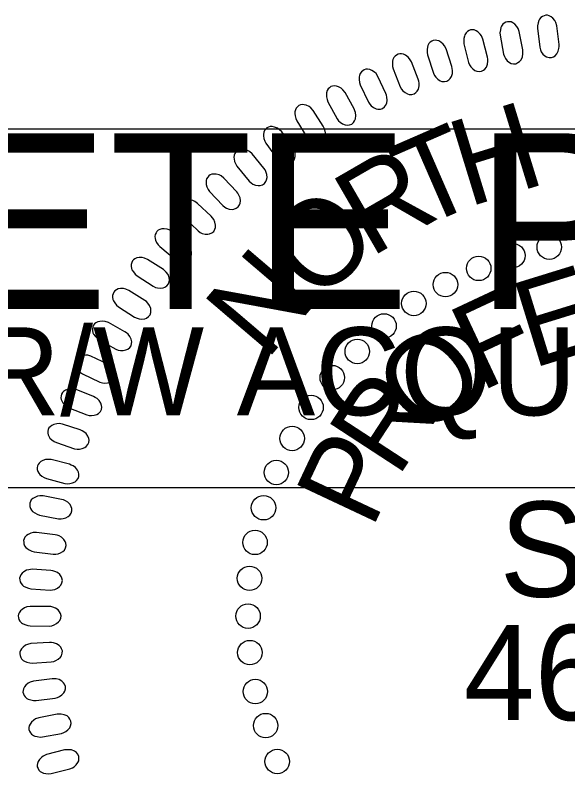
# Model space of a CAD drawing. Extents: x 502400 to 509344, y 448070 to 484209.
# Drawn here: x 507178.88 to 507215.05, y 484083.77 to 484133.46 of the extents above; entities that cross this region are included whole.
import ezdxf

# ---------------------------------------------------------------- set-up
doc = ezdxf.new("R2010")
doc.units = 0
doc.layers.add('Sheet PE Seal Cell', color=7, linetype='Continuous')
doc.layers.add('Sheet Sticker Incomplete CELL', color=7, linetype='Continuous')

msp = doc.modelspace()

# ---------------------------------------------------------------- linework, layer by layer
at = {"layer": 'Sheet PE Seal Cell'}
for points in [[(507212.1, 484131.181), (507211.871, 484132.386), (507211.793, 484132.594), (507211.716, 484132.722), (507211.574, 484132.868), (507211.458, 484132.957), (507211.333, 484133.015), (507211.223, 484133.034), (507211.109, 484133.033), (507211.002, 484132.992), (507210.891, 484132.94), (507210.799, 484132.862), (507210.714, 484132.744), (507210.671, 484132.655), (507210.633, 484132.495), (507210.608, 484132.308), (507210.615, 484132.147), (507210.843, 484130.911), (507210.897, 484130.749), (507210.967, 484130.62), (507211.085, 484130.48), (507211.221, 484130.364), (507211.332, 484130.304), (507211.497, 484130.274), (507211.647, 484130.283), (507211.787, 484130.35), (507211.881, 484130.419), (507211.987, 484130.54), (507212.073, 484130.729), (507212.105, 484130.918), (507212.11, 484131.051)], [(507214.482, 484131.549), (507214.328, 484132.766), (507214.264, 484132.98), (507214.194, 484133.111), (507214.062, 484133.266), (507213.952, 484133.362), (507213.831, 484133.427), (507213.722, 484133.454), (507213.608, 484133.46), (507213.499, 484133.426), (507213.384, 484133.381), (507213.288, 484133.309), (507213.196, 484133.197), (507213.147, 484133.11), (507213.099, 484132.953), (507213.062, 484132.768), (507213.06, 484132.607), (507213.21, 484131.359), (507213.253, 484131.194), (507213.315, 484131.06), (507213.424, 484130.913), (507213.553, 484130.789), (507213.659, 484130.722), (507213.822, 484130.682), (507213.973, 484130.681), (507214.116, 484130.739), (507214.214, 484130.802), (507214.328, 484130.917), (507214.425, 484131.1), (507214.469, 484131.286), (507214.483, 484131.419)], [(507209.795, 484130.709), (507209.491, 484131.897), (507209.4, 484132.1), (507209.314, 484132.223), (507209.164, 484132.359), (507209.042, 484132.441), (507208.914, 484132.491), (507208.802, 484132.504), (507208.689, 484132.495), (507208.585, 484132.448), (507208.477, 484132.389), (507208.39, 484132.305), (507208.314, 484132.182), (507208.276, 484132.091), (507208.247, 484131.929), (507208.234, 484131.74), (507208.252, 484131.58), (507208.557, 484130.361), (507208.621, 484130.202), (507208.699, 484130.078), (507208.826, 484129.946), (507208.969, 484129.838), (507209.083, 484129.786), (507209.25, 484129.766), (507209.4, 484129.784), (507209.535, 484129.86), (507209.624, 484129.934), (507209.722, 484130.062), (507209.795, 484130.256), (507209.816, 484130.447), (507209.813, 484130.579)], [(507207.461, 484130.088), (507207.083, 484131.255), (507206.98, 484131.452), (507206.887, 484131.569), (507206.728, 484131.696), (507206.602, 484131.77), (507206.47, 484131.811), (507206.358, 484131.817), (507206.246, 484131.801), (507206.145, 484131.748), (507206.041, 484131.682), (507205.96, 484131.594), (507205.891, 484131.466), (507205.859, 484131.372), (507205.84, 484131.208), (507205.839, 484131.019), (507205.867, 484130.86), (507206.248, 484129.663), (507206.322, 484129.509), (507206.407, 484129.39), (507206.542, 484129.266), (507206.692, 484129.168), (507206.809, 484129.122), (507206.977, 484129.113), (507207.125, 484129.14), (507207.255, 484129.224), (507207.339, 484129.304), (507207.429, 484129.438), (507207.49, 484129.637), (507207.499, 484129.828), (507207.487, 484129.961)], [(507205.261, 484129.272), (507204.809, 484130.413), (507204.694, 484130.603), (507204.594, 484130.714), (507204.427, 484130.83), (507204.297, 484130.897), (507204.163, 484130.929), (507204.051, 484130.928), (507203.94, 484130.905), (507203.843, 484130.845), (507203.742, 484130.773), (507203.667, 484130.679), (507203.606, 484130.548), (507203.58, 484130.452), (507203.572, 484130.288), (507203.583, 484130.099), (507203.621, 484129.943), (507204.076, 484128.771), (507204.159, 484128.622), (507204.253, 484128.509), (507204.395, 484128.393), (507204.55, 484128.305), (507204.67, 484128.266), (507204.838, 484128.268), (507204.984, 484128.305), (507205.108, 484128.397), (507205.187, 484128.482), (507205.269, 484128.621), (507205.318, 484128.823), (507205.314, 484129.015), (507205.295, 484129.146)], [(507203.143, 484128.339), (507202.621, 484129.449), (507202.494, 484129.631), (507202.387, 484129.736), (507202.214, 484129.842), (507202.079, 484129.9), (507201.944, 484129.924), (507201.832, 484129.916), (507201.722, 484129.886), (507201.629, 484129.82), (507201.534, 484129.743), (507201.464, 484129.644), (507201.412, 484129.509), (507201.392, 484129.411), (507201.395, 484129.247), (507201.417, 484129.059), (507201.464, 484128.905), (507201.993, 484127.766), (507202.085, 484127.621), (507202.185, 484127.514), (507202.334, 484127.408), (507202.495, 484127.329), (507202.617, 484127.298), (507202.784, 484127.311), (507202.928, 484127.356), (507203.046, 484127.456), (507203.12, 484127.546), (507203.192, 484127.69), (507203.229, 484127.894), (507203.213, 484128.085), (507203.185, 484128.216)], [(507201.06, 484127.325), (507200.469, 484128.401), (507200.331, 484128.575), (507200.218, 484128.672), (507200.038, 484128.767), (507199.9, 484128.816), (507199.764, 484128.832), (507199.653, 484128.816), (507199.545, 484128.78), (507199.456, 484128.709), (507199.366, 484128.625), (507199.303, 484128.522), (507199.259, 484128.384), (507199.245, 484128.285), (507199.258, 484128.122), (507199.292, 484127.935), (507199.349, 484127.785), (507199.948, 484126.68), (507200.049, 484126.542), (507200.156, 484126.442), (507200.311, 484126.345), (507200.477, 484126.276), (507200.6, 484126.253), (507200.767, 484126.276), (507200.907, 484126.331), (507201.019, 484126.438), (507201.087, 484126.532), (507201.15, 484126.681), (507201.173, 484126.887), (507201.146, 484127.077), (507201.109, 484127.204)], [(507199.043, 484126.183), (507198.386, 484127.219), (507198.237, 484127.385), (507198.118, 484127.474), (507197.933, 484127.558), (507197.792, 484127.598), (507197.655, 484127.606), (507197.544, 484127.583), (507197.439, 484127.54), (507197.355, 484127.463), (507197.27, 484127.374), (507197.214, 484127.267), (507197.179, 484127.127), (507197.171, 484127.028), (507197.194, 484126.865), (507197.24, 484126.682), (507197.306, 484126.534), (507197.973, 484125.469), (507198.083, 484125.338), (507198.196, 484125.244), (507198.357, 484125.158), (507198.526, 484125.1), (507198.651, 484125.084), (507198.816, 484125.118), (507198.952, 484125.181), (507199.058, 484125.295), (507199.119, 484125.393), (507199.173, 484125.545), (507199.183, 484125.753), (507199.144, 484125.941), (507199.1, 484126.065)], [(507197.042, 484124.829), (507196.321, 484125.821), (507196.162, 484125.977), (507196.038, 484126.059), (507195.847, 484126.131), (507195.704, 484126.162), (507195.567, 484126.161), (507195.458, 484126.132), (507195.356, 484126.082), (507195.277, 484126), (507195.198, 484125.906), (507195.149, 484125.796), (507195.122, 484125.653), (507195.121, 484125.554), (507195.155, 484125.393), (507195.211, 484125.213), (507195.287, 484125.07), (507196.019, 484124.049), (507196.137, 484123.925), (507196.255, 484123.838), (507196.421, 484123.762), (507196.594, 484123.715), (507196.72, 484123.707), (507196.882, 484123.751), (507197.015, 484123.823), (507197.112, 484123.943), (507197.167, 484124.045), (507197.212, 484124.2), (507197.209, 484124.408), (507197.158, 484124.593), (507197.106, 484124.715)], [(507195.162, 484123.44), (507194.38, 484124.385), (507194.212, 484124.53), (507194.082, 484124.605), (507193.888, 484124.664), (507193.743, 484124.687), (507193.606, 484124.677), (507193.5, 484124.64), (507193.401, 484124.584), (507193.327, 484124.497), (507193.254, 484124.398), (507193.211, 484124.286), (507193.194, 484124.142), (507193.199, 484124.042), (507193.242, 484123.884), (507193.31, 484123.708), (507193.395, 484123.57), (507194.189, 484122.597), (507194.315, 484122.481), (507194.439, 484122.402), (507194.609, 484122.336), (507194.785, 484122.3), (507194.911, 484122.3), (507195.07, 484122.354), (507195.198, 484122.434), (507195.287, 484122.56), (507195.336, 484122.665), (507195.371, 484122.823), (507195.354, 484123.03), (507195.292, 484123.211), (507195.232, 484123.33)], [(507193.374, 484121.9), (507192.535, 484122.795), (507192.357, 484122.93), (507192.223, 484122.996), (507192.025, 484123.043), (507191.88, 484123.056), (507191.744, 484123.038), (507191.64, 484122.995), (507191.544, 484122.933), (507191.476, 484122.842), (507191.409, 484122.738), (507191.374, 484122.623), (507191.366, 484122.478), (507191.377, 484122.379), (507191.43, 484122.224), (507191.51, 484122.052), (507191.602, 484121.921), (507192.457, 484120.999), (507192.589, 484120.891), (507192.717, 484120.82), (507192.892, 484120.765), (507193.07, 484120.739), (507193.195, 484120.747), (507193.35, 484120.812), (507193.473, 484120.9), (507193.554, 484121.031), (507193.597, 484121.139), (507193.622, 484121.299), (507193.593, 484121.504), (507193.518, 484121.681), (507193.452, 484121.796)], [(507191.712, 484120.291), (507190.818, 484121.131), (507190.632, 484121.254), (507190.495, 484121.312), (507190.294, 484121.346), (507190.148, 484121.351), (507190.013, 484121.323), (507189.912, 484121.274), (507189.821, 484121.206), (507189.759, 484121.111), (507189.699, 484121.003), (507189.67, 484120.887), (507189.671, 484120.742), (507189.689, 484120.643), (507189.751, 484120.492), (507189.841, 484120.326), (507189.942, 484120.199), (507190.853, 484119.334), (507190.992, 484119.234), (507191.124, 484119.171), (507191.302, 484119.127), (507191.48, 484119.114), (507191.605, 484119.129), (507191.757, 484119.203), (507191.873, 484119.298), (507191.946, 484119.435), (507191.982, 484119.545), (507191.996, 484119.706), (507191.955, 484119.909), (507191.87, 484120.081), (507191.796, 484120.191)], [(507190.098, 484118.504), (507189.154, 484119.287), (507188.96, 484119.398), (507188.82, 484119.447), (507188.617, 484119.468), (507188.471, 484119.464), (507188.339, 484119.428), (507188.241, 484119.373), (507188.154, 484119.299), (507188.098, 484119.2), (507188.045, 484119.088), (507188.024, 484118.97), (507188.034, 484118.826), (507188.057, 484118.729), (507188.13, 484118.582), (507188.23, 484118.421), (507188.338, 484118.302), (507189.301, 484117.495), (507189.446, 484117.404), (507189.583, 484117.35), (507189.763, 484117.317), (507189.941, 484117.314), (507190.065, 484117.339), (507190.211, 484117.421), (507190.322, 484117.523), (507190.387, 484117.664), (507190.415, 484117.777), (507190.419, 484117.938), (507190.365, 484118.138), (507190.27, 484118.305), (507190.188, 484118.41)], [(507188.574, 484116.802), (507187.544, 484117.468), (507187.339, 484117.555), (507187.193, 484117.588), (507186.99, 484117.586), (507186.845, 484117.563), (507186.718, 484117.512), (507186.628, 484117.446), (507186.55, 484117.363), (507186.505, 484117.258), (507186.466, 484117.141), (507186.459, 484117.021), (507186.486, 484116.879), (507186.52, 484116.785), (507186.61, 484116.648), (507186.728, 484116.499), (507186.85, 484116.394), (507187.901, 484115.706), (507188.056, 484115.633), (507188.197, 484115.595), (507188.38, 484115.584), (507188.558, 484115.602), (507188.678, 484115.641), (507188.813, 484115.74), (507188.911, 484115.854), (507188.959, 484116.002), (507188.974, 484116.117), (507188.959, 484116.278), (507188.882, 484116.47), (507188.767, 484116.624), (507188.674, 484116.719)], [(507187.359, 484114.779), (507186.324, 484115.437), (507186.119, 484115.523), (507185.973, 484115.554), (507185.769, 484115.551), (507185.625, 484115.527), (507185.497, 484115.475), (507185.408, 484115.408), (507185.33, 484115.324), (507185.287, 484115.218), (507185.249, 484115.102), (507185.243, 484114.981), (507185.271, 484114.84), (507185.306, 484114.746), (507185.397, 484114.609), (507185.516, 484114.462), (507185.639, 484114.358), (507186.696, 484113.678), (507186.851, 484113.606), (507186.993, 484113.569), (507187.175, 484113.559), (507187.353, 484113.579), (507187.473, 484113.618), (507187.607, 484113.719), (507187.704, 484113.835), (507187.751, 484113.982), (507187.765, 484114.097), (507187.749, 484114.258), (507187.67, 484114.449), (507187.554, 484114.603), (507187.461, 484114.698)], [(507186.056, 484112.73), (507184.981, 484113.322), (507184.771, 484113.395), (507184.623, 484113.416), (507184.421, 484113.4), (507184.277, 484113.367), (507184.154, 484113.308), (507184.069, 484113.235), (507183.997, 484113.147), (507183.961, 484113.039), (507183.929, 484112.92), (507183.931, 484112.799), (507183.968, 484112.659), (507184.009, 484112.569), (507184.107, 484112.437), (507184.236, 484112.298), (507184.365, 484112.202), (507185.462, 484111.59), (507185.621, 484111.527), (507185.765, 484111.5), (507185.949, 484111.501), (507186.125, 484111.532), (507186.242, 484111.579), (507186.37, 484111.687), (507186.459, 484111.809), (507186.496, 484111.959), (507186.503, 484112.074), (507186.477, 484112.234), (507186.386, 484112.42), (507186.262, 484112.566), (507186.162, 484112.655)], [(507184.947, 484110.606), (507183.837, 484111.129), (507183.623, 484111.189), (507183.474, 484111.201), (507183.273, 484111.172), (507183.132, 484111.131), (507183.013, 484111.063), (507182.932, 484110.985), (507182.866, 484110.892), (507182.836, 484110.783), (507182.813, 484110.661), (507182.822, 484110.542), (507182.868, 484110.405), (507182.914, 484110.317), (507183.021, 484110.192), (507183.158, 484110.061), (507183.292, 484109.972), (507184.427, 484109.43), (507184.589, 484109.379), (507184.735, 484109.36), (507184.917, 484109.373), (507185.091, 484109.415), (507185.205, 484109.469), (507185.326, 484109.585), (507185.408, 484109.712), (507185.435, 484109.864), (507185.435, 484109.981), (507185.399, 484110.138), (507185.297, 484110.318), (507185.163, 484110.455), (507185.058, 484110.538)], [(507184.008, 484108.488), (507182.868, 484108.939), (507182.65, 484108.985), (507182.501, 484108.989), (507182.302, 484108.947), (507182.164, 484108.897), (507182.049, 484108.822), (507181.973, 484108.739), (507181.913, 484108.642), (507181.89, 484108.531), (507181.874, 484108.408), (507181.891, 484108.289), (507181.945, 484108.156), (507181.997, 484108.07), (507182.112, 484107.952), (507182.257, 484107.831), (507182.396, 484107.751), (507183.562, 484107.281), (507183.727, 484107.24), (507183.874, 484107.23), (507184.055, 484107.254), (507184.226, 484107.307), (507184.337, 484107.368), (507184.451, 484107.492), (507184.524, 484107.623), (507184.542, 484107.777), (507184.534, 484107.893), (507184.488, 484108.048), (507184.374, 484108.221), (507184.232, 484108.35), (507184.122, 484108.426)], [(507183.132, 484106.298), (507181.965, 484106.678), (507181.745, 484106.71), (507181.596, 484106.704), (507181.4, 484106.65), (507181.265, 484106.591), (507181.155, 484106.509), (507181.085, 484106.422), (507181.032, 484106.321), (507181.016, 484106.209), (507181.007, 484106.086), (507181.032, 484105.968), (507181.094, 484105.837), (507181.152, 484105.756), (507181.273, 484105.645), (507181.425, 484105.533), (507181.57, 484105.462), (507182.763, 484105.066), (507182.931, 484105.035), (507183.078, 484105.035), (507183.257, 484105.071), (507183.424, 484105.134), (507183.531, 484105.202), (507183.636, 484105.332), (507183.701, 484105.469), (507183.709, 484105.623), (507183.694, 484105.738), (507183.639, 484105.89), (507183.515, 484106.056), (507183.364, 484106.176), (507183.25, 484106.244)], [(507182.428, 484104.043), (507181.239, 484104.348), (507181.018, 484104.366), (507180.869, 484104.351), (507180.677, 484104.284), (507180.547, 484104.218), (507180.441, 484104.129), (507180.377, 484104.037), (507180.329, 484103.934), (507180.321, 484103.821), (507180.32, 484103.697), (507180.352, 484103.58), (507180.423, 484103.455), (507180.485, 484103.377), (507180.613, 484103.274), (507180.772, 484103.172), (507180.921, 484103.11), (507182.136, 484102.79), (507182.306, 484102.77), (507182.452, 484102.778), (507182.629, 484102.826), (507182.792, 484102.899), (507182.894, 484102.974), (507182.991, 484103.111), (507183.047, 484103.251), (507183.046, 484103.405), (507183.024, 484103.519), (507182.959, 484103.667), (507182.825, 484103.825), (507182.667, 484103.935), (507182.549, 484103.996)], [(507181.916, 484101.747), (507180.712, 484101.977), (507180.489, 484101.982), (507180.342, 484101.957), (507180.154, 484101.878), (507180.028, 484101.804), (507179.929, 484101.708), (507179.87, 484101.613), (507179.829, 484101.507), (507179.828, 484101.393), (507179.835, 484101.27), (507179.874, 484101.156), (507179.952, 484101.034), (507180.019, 484100.961), (507180.154, 484100.866), (507180.319, 484100.774), (507180.471, 484100.722), (507181.705, 484100.478), (507181.875, 484100.469), (507182.021, 484100.487), (507182.194, 484100.545), (507182.352, 484100.629), (507182.449, 484100.71), (507182.537, 484100.852), (507182.585, 484100.996), (507182.574, 484101.15), (507182.544, 484101.262), (507182.47, 484101.406), (507182.327, 484101.555), (507182.162, 484101.655), (507182.041, 484101.708)], [(507181.496, 484099.433), (507180.279, 484099.587), (507180.057, 484099.577), (507179.911, 484099.543), (507179.729, 484099.453), (507179.608, 484099.371), (507179.515, 484099.269), (507179.462, 484099.171), (507179.428, 484099.062), (507179.434, 484098.948), (507179.449, 484098.826), (507179.495, 484098.714), (507179.581, 484098.598), (507179.653, 484098.529), (507179.792, 484098.443), (507179.963, 484098.361), (507180.118, 484098.319), (507181.364, 484098.154), (507181.535, 484098.155), (507181.679, 484098.182), (507181.848, 484098.25), (507182.001, 484098.344), (507182.093, 484098.431), (507182.172, 484098.579), (507182.211, 484098.725), (507182.189, 484098.878), (507182.153, 484098.988), (507182.07, 484099.127), (507181.917, 484099.266), (507181.747, 484099.356), (507181.623, 484099.402)], [(507181.21, 484097.089), (507179.985, 484097.166), (507179.764, 484097.143), (507179.621, 484097.1), (507179.445, 484096.999), (507179.329, 484096.908), (507179.242, 484096.802), (507179.196, 484096.699), (507179.169, 484096.589), (507179.182, 484096.476), (507179.205, 484096.354), (507179.257, 484096.246), (507179.35, 484096.136), (507179.426, 484096.071), (507179.571, 484095.994), (507179.746, 484095.923), (507179.904, 484095.891), (507181.158, 484095.804), (507181.329, 484095.815), (507181.471, 484095.852), (507181.636, 484095.931), (507181.782, 484096.034), (507181.868, 484096.126), (507181.937, 484096.279), (507181.967, 484096.427), (507181.936, 484096.578), (507181.893, 484096.686), (507181.802, 484096.819), (507181.64, 484096.949), (507181.465, 484097.028), (507181.338, 484097.065)], [(507181.08, 484094.738), (507179.853, 484094.738), (507179.634, 484094.701), (507179.493, 484094.649), (507179.324, 484094.537), (507179.214, 484094.44), (507179.135, 484094.327), (507179.095, 484094.223), (507179.075, 484094.11), (507179.095, 484093.999), (507179.124, 484093.879), (507179.184, 484093.774), (507179.284, 484093.67), (507179.364, 484093.61), (507179.513, 484093.542), (507179.693, 484093.483), (507179.852, 484093.46), (507181.109, 484093.452), (507181.278, 484093.474), (507181.418, 484093.52), (507181.577, 484093.609), (507181.717, 484093.721), (507181.797, 484093.818), (507181.857, 484093.975), (507181.877, 484094.125), (507181.837, 484094.274), (507181.787, 484094.379), (507181.688, 484094.507), (507181.518, 484094.626), (507181.339, 484094.693), (507181.209, 484094.723)], [(507181.132, 484092.38), (507179.907, 484092.304), (507179.691, 484092.253), (507179.555, 484092.192), (507179.392, 484092.069), (507179.288, 484091.965), (507179.216, 484091.848), (507179.183, 484091.742), (507179.171, 484091.628), (507179.198, 484091.518), (507179.235, 484091.4), (507179.3, 484091.3), (507179.407, 484091.202), (507179.49, 484091.147), (507179.644, 484091.089), (507179.827, 484091.041), (507179.987, 484091.028), (507181.242, 484091.099), (507181.41, 484091.132), (507181.546, 484091.186), (507181.7, 484091.286), (507181.832, 484091.406), (507181.906, 484091.507), (507181.956, 484091.668), (507181.966, 484091.819), (507181.917, 484091.965), (507181.861, 484092.067), (507181.753, 484092.187), (507181.577, 484092.296), (507181.393, 484092.352), (507181.262, 484092.374)], [(507181.297, 484089.999), (507180.079, 484089.846), (507179.867, 484089.781), (507179.734, 484089.712), (507179.58, 484089.58), (507179.483, 484089.469), (507179.418, 484089.348), (507179.392, 484089.24), (507179.386, 484089.125), (507179.42, 484089.017), (507179.465, 484088.902), (507179.537, 484088.805), (507179.649, 484088.714), (507179.736, 484088.665), (507179.892, 484088.617), (507180.078, 484088.58), (507180.239, 484088.578), (507181.487, 484088.727), (507181.652, 484088.771), (507181.785, 484088.833), (507181.932, 484088.942), (507182.057, 484089.07), (507182.124, 484089.176), (507182.164, 484089.34), (507182.164, 484089.491), (507182.106, 484089.634), (507182.044, 484089.732), (507181.929, 484089.846), (507181.746, 484089.943), (507181.559, 484089.987), (507181.427, 484090)], [(507181.63, 484087.674), (507180.425, 484087.444), (507180.216, 484087.367), (507180.089, 484087.29), (507179.943, 484087.147), (507179.853, 484087.031), (507179.796, 484086.906), (507179.777, 484086.796), (507179.778, 484086.682), (507179.819, 484086.576), (507179.871, 484086.464), (507179.948, 484086.372), (507180.067, 484086.288), (507180.156, 484086.244), (507180.316, 484086.206), (507180.503, 484086.181), (507180.664, 484086.189), (507181.9, 484086.417), (507182.062, 484086.47), (507182.191, 484086.54), (507182.33, 484086.658), (507182.447, 484086.795), (507182.507, 484086.905), (507182.537, 484087.07), (507182.528, 484087.221), (507182.461, 484087.36), (507182.393, 484087.454), (507182.271, 484087.56), (507182.082, 484087.646), (507181.892, 484087.678), (507181.76, 484087.683)], [(507182.11, 484085.333), (507180.921, 484085.028), (507180.718, 484084.937), (507180.595, 484084.852), (507180.459, 484084.701), (507180.377, 484084.58), (507180.328, 484084.451), (507180.315, 484084.34), (507180.324, 484084.226), (507180.371, 484084.123), (507180.429, 484084.015), (507180.513, 484083.928), (507180.636, 484083.852), (507180.728, 484083.813), (507180.89, 484083.785), (507181.079, 484083.772), (507181.239, 484083.79), (507182.458, 484084.094), (507182.617, 484084.158), (507182.74, 484084.237), (507182.873, 484084.363), (507182.98, 484084.506), (507183.033, 484084.62), (507183.052, 484084.788), (507183.034, 484084.937), (507182.959, 484085.072), (507182.884, 484085.161), (507182.756, 484085.26), (507182.562, 484085.333), (507182.371, 484085.354), (507182.239, 484085.35)]]:
    msp.add_lwpolyline(points, close=True, dxfattribs=at)
for centre in [(507213.835, 484118.268), (507211.446, 484117.711), (507209.216, 484116.875), (507207.041, 484115.814), (507204.971, 484114.58), (507203.019, 484113.106), (507201.267, 484111.434), (507199.634, 484109.721), (507198.24, 484107.77), (507197.005, 484105.738), (507195.969, 484103.508), (507195.132, 484101.198), (507194.574, 484098.927), (507194.215, 484096.577), (507194.119, 484094.102), (507194.237, 484091.712), (507194.595, 484089.162), (507195.271, 484086.931), (507196.027, 484084.581)]:
    msp.add_circle(centre, 0.801, dxfattribs=at)
at = {"layer": 'Sheet Sticker Incomplete CELL'}
msp.add_lwpolyline([(507095.597, 484102.505), (507095.597, 484126.005), (507242.597, 484126.005), (507242.597, 484102.505)], close=True, dxfattribs=at)

# ---------------------------------------------------------------- texts
at = {"layer": 'Sheet PE Seal Cell'}
for s, height, rotation, p in [('H', 5.669, 17.0557, (507208.505, 484120.872)), ('T', 5.669, 23.5451, (507205.326, 484119.462)), ('R', 5.669, 30.0345, (507202.105, 484117.543)), ('O', 5.669, 43.0132, (507198.63, 484114.515)), ('N', 5.669, 49.5025, (507195.283, 484110.76)), ('E', 5.669, 17.1686, (507212.701, 484110.303)), ('F', 5.669, 25.1084, (507209.311, 484108.764)), ('O', 5.669, 40.988, (507205.614, 484105.626)), ('R', 5.669, 56.8676, (507203.9, 484103.08)), ('P', 5.669, 64.8074, (507202.214, 484099.718)), ('SEAL', 6.2363, 359.9814, (507210.585, 484095.369)), ('46155', 6.2363, 359.9814, (507208.236, 484087.29))]:
    msp.add_text(s, height=height, rotation=rotation, dxfattribs=at).set_placement(p)
at = {"layer": 'Sheet Sticker Incomplete CELL'}
for s, height, p in [('INCOMPLETE PLANS', 11.52, (507104.547, 484114.205)), ('DO NOT USE FOR R/W ACQUISITION', 5.76, (507107.797, 484107.255))]:
    msp.add_text(s, height=height, dxfattribs=at).set_placement(p)

doc.saveas('drawing.dxf')
